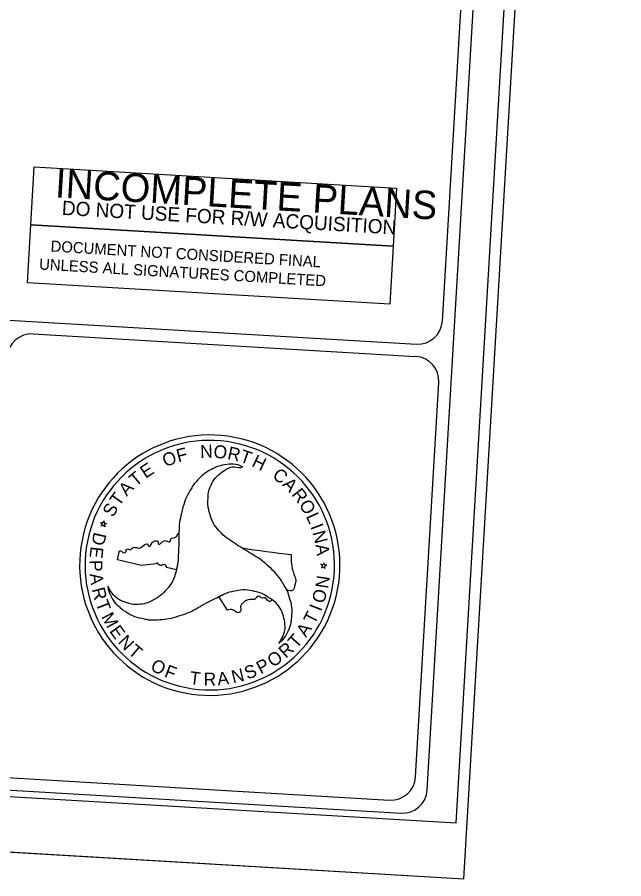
# Model space of a CAD drawing. Extents: x 1998567 to 2027801, y 439108 to 451079.
# Drawn here: x 2018763 to 2021220, y 439108 to 442597 of the extents above; entities that cross this region are included whole.
import ezdxf

# ---------------------------------------------------------------- set-up
doc = ezdxf.new("R2010")
doc.units = 0
for name, color, linetype in [('Sheet Cutting Line CELL', 7, 'Continuous'), ('Sheet Plot Border Inside CELL', 7, 'Continuous'), ('Sheet Plot Border Outside CELL', 7, 'Continuous'), ('Sheet Sticker Exception Certification CELL', 7, 'Continuous'), ('Sheet Sticker Incomplete CELL', 7, 'Continuous'), ('Sheet Title CELL', 7, 'Continuous')]:
    doc.layers.add(name, color=color, linetype=linetype)

msp = doc.modelspace()

# ---------------------------------------------------------------- linework, layer by layer
at = {"layer": 'Sheet Cutting Line CELL'}
msp.add_line((2003762.2, 440098.6), (2020573, 439107.6), dxfattribs=at)
at = {"layer": 'Sheet Plot Border Inside CELL'}
msp.add_lwpolyline([(2003905.2, 440314.9), (2020541.3, 439334.2), (2021162.2, 449866.9), (2004526.1, 450847.6)], close=True, dxfattribs=at)
at = {"layer": 'Sheet Plot Border Outside CELL'}
msp.add_lwpolyline([(2021220.3, 450088.4), (2004409.5, 451079.4), (2003762.2, 440098.6), (2020573, 439107.6)], close=True, dxfattribs=at)
at = {"layer": 'Sheet Sticker Exception Certification CELL'}
for p, q in [((2018804.5, 441521.7), (2018818.3, 441756.3)), ((2018818.3, 441756.3), (2020285.8, 441669.8)), ((2020285.8, 441669.7), (2020272, 441435.1)), ((2020272, 441435.2), (2018804.5, 441521.7))]:
    msp.add_line(p, q, dxfattribs=at)
at = {"layer": 'Sheet Sticker Incomplete CELL'}
msp.add_lwpolyline([(2018818.3, 441756.3), (2018832.2, 441990.9), (2020299.6, 441904.4), (2020285.8, 441669.8)], close=True, dxfattribs=at)
at = {"layer": 'Sheet Title CELL'}
for p, q in [((2006204.7, 442108.3), (2020380.1, 441272.7)), ((2018827.5, 441314.1), (2020377.1, 441222.8)), ((2019677.5, 440777.1), (2019676.3, 440776.2)), ((2019677.5, 440777.1), (2019676.3, 440776.2)), ((2019107.5, 440544.3), (2019101.4, 440551.1)), ((2019101.4, 440551.1), (2019110.4, 440549.3)), ((2019110.4, 440549.3), (2019114.5, 440557.1)), ((2019114.5, 440557.1), (2019115.9, 440548.3)), ((2019103.3, 440536.2), (2019107.5, 440544.3)), ((2019111.2, 440540.3), (2019103.3, 440536.2)), ((2019117.5, 440533.5), (2019111.2, 440540.3)), ((2019115.9, 440548.3), (2019124.8, 440546.5)), ((2019124.8, 440546.5), (2019116.4, 440542.6)), ((2019116.4, 440542.6), (2019117.5, 440533.5)), ((2019671.3, 440448.6), (2019671.3, 440448.6)), ((2019169.2, 440399.7), (2019176.3, 440430.6)), ((2019266.6, 440377), (2019169.2, 440399.7)), ((2019326.1, 440382.6), (2019266.6, 440377)), ((2020002.6, 440379.7), (2019993.7, 440381.4)), ((2019993.7, 440381.4), (2020000, 440374.8)), ((2020000, 440374.8), (2019995.8, 440366.7)), ((2020006.9, 440387.4), (2020002.6, 440379.7)), ((2020008.4, 440378.6), (2020006.9, 440387.4)), ((2020017.2, 440377.2), (2020008.4, 440378.6)), ((2020008.9, 440373.1), (2020017.2, 440377.2)), ((2019409, 440359.4), (2019368.1, 440367.8)), ((2019995.8, 440366.7), (2020003.7, 440370.6)), ((2020003.7, 440370.6), (2020009.9, 440364)), ((2020009.9, 440364), (2020008.9, 440373.1)), ((2020060.8, 440277.7), (2020060.8, 440277.7)), ((2019614.6, 440195), (2019580.3, 440250.5)), ((2019580.3, 440250.5), (2019580.3, 440250.5))]:
    msp.add_line(p, q, dxfattribs=at)
for points in [[(2020423.9, 439467), (2021030, 449749)], [(2020485.8, 441366.5), (2020977.2, 449702.2)], [(2020376.9, 439519.9), (2020471.1, 441117.1)], [(2005543.8, 440243.8), (2020318.2, 439372.9)], [(2018721.7, 439517.3), (2020271.2, 439425.9)]]:
    msp.add_lwpolyline(points, dxfattribs=at)
for centre, radius, start, end in [((2020386, 441373), 100, 266.6264, 356.6264), ((2018821.7, 441214.3), 100, 86.6264, 176.6264), ((2020371.3, 441123.4), 100, 356.6264, 86.6264), ((2019543.3, 440377.7), 527.2, 349.0476, 169.0476), ((2019543.3, 440377.7), 505.2, 349.0476, 169.0476), ((2020146.1, 443187.2), 2779.4, 254.7261, 254.8256), ((2019543.3, 440377.7), 527.2, 169.0476, 349.0476), ((2019543.3, 440377.7), 505.2, 169.0476, 349.0476), ((2020146.1, 443187.2), 2779.4, 260.1651, 264.3711), ((2020277.2, 439526.2), 100, 266.6264, 356.6264), ((2020324.1, 439473.3), 100, 266.6264, 356.6264)]:
    msp.add_arc(centre, radius, start, end, dxfattribs=at)
for points in [[(2019676.3, 440776.2), (2019665.3, 440781.6), (2019630.7, 440786.8), (2019593.5, 440782.4), (2019590.1, 440781.3), (2019570.8, 440775.5), (2019549.6, 440765.3), (2019516.4, 440744.2), (2019488.6, 440715.7), (2019477.3, 440703.4), (2019467.7, 440687.4), (2019449.1, 440653.1), (2019436.3, 440619), (2019426, 440578.2), (2019419.6, 440541.8), (2019418.5, 440503.7), (2019417.7, 440465.2), (2019416.1, 440428), (2019413.9, 440389.7), (2019406.9, 440352.7), (2019406.1, 440349.5), (2019391.9, 440311.4), (2019369.3, 440279.9), (2019343.1, 440254.9), (2019328.4, 440243.9), (2019308.5, 440233.8), (2019297.1, 440227.8), (2019271.3, 440220.4), (2019234.3, 440219), (2019200, 440227.7), (2019170.8, 440241.5), (2019147.2, 440264), (2019130.7, 440293)], [(2019822.4, 440062.2), (2019832, 440068.9), (2019854.2, 440096.3), (2019868.9, 440130.7), (2019870.1, 440134.2), (2019874.2, 440153.9), (2019876.1, 440177.6), (2019874.8, 440216.8), (2019863.5, 440254.9), (2019858.8, 440271), (2019849.6, 440287.5), (2019829.3, 440320.6), (2019806.2, 440348.8), (2019775.9, 440377.9), (2019747.5, 440401.4), (2019715.1, 440422), (2019682.3, 440441.7), (2019651.1, 440461.6), (2019618.5, 440482.8), (2019590.2, 440507.2), (2019588, 440509.7), (2019561.6, 440541.3), (2019545.9, 440576.6), (2019537.1, 440611.6), (2019535.4, 440629.6), (2019536.6, 440652.1), (2019536.8, 440665.1), (2019543.6, 440690.8), (2019560.9, 440724), (2019585.3, 440749), (2019611.9, 440767.2), (2019643.4, 440776.4), (2019676.3, 440776.2), (2019677.5, 440777.1)], [(2019176.3, 440430.6), (2019175.7, 440433.7), (2019181.6, 440436.1), (2019195, 440427.3), (2019203.6, 440432.1), (2019204.5, 440438.5), (2019211.6, 440443.7), (2019221.1, 440439.7), (2019232.4, 440449.5), (2019241.1, 440449.9), (2019258.6, 440446.5), (2019283.3, 440463.3), (2019292.3, 440462.9), (2019293.4, 440456.9), (2019298.6, 440454.8), (2019310.8, 440470.3), (2019313.6, 440472.3), (2019331.1, 440475.6), (2019334.8, 440471.7), (2019334.5, 440463.8), (2019336.5, 440461.8), (2019342.6, 440464.6), (2019351.6, 440472.4), (2019366.3, 440476.7), (2019381.1, 440472), (2019386.1, 440483.9), (2019406.2, 440492.4), (2019411.3, 440498.9), (2019413.7, 440506.1)], [(2019418.5, 440504.7), (2019418.5, 440503.7), (2019417.7, 440465.2), (2019416.1, 440428), (2019413.9, 440389.7), (2019408.9, 440359.5)], [(2019856.1, 440277.2), (2019849.6, 440287.5), (2019829.3, 440320.6), (2019806.2, 440348.8), (2019775.9, 440377.9), (2019747.5, 440401.4), (2019715.1, 440422), (2019682.3, 440441.7), (2019671.3, 440448.6)], [(2019873.4, 440421.1), (2019874.1, 440385.1), (2019884.3, 440341), (2019891.7, 440316.5), (2019887.7, 440297.4), (2019878.8, 440275.4), (2019856.2, 440277.4)], [(2019368.1, 440367.8), (2019365.6, 440376.1), (2019358.1, 440380), (2019346.2, 440376.4), (2019338.2, 440378.4), (2019330.5, 440386.6), (2019326.1, 440382.6)], [(2019130.7, 440293), (2019132.1, 440280.6), (2019144.7, 440247.9), (2019166.9, 440217.9), (2019169.5, 440215.8), (2019184.5, 440201.6), (2019203.9, 440188.6), (2019238.8, 440170), (2019277.1, 440160.7), (2019293.4, 440156.8), (2019312.9, 440156.5), (2019351, 440157.7), (2019386.8, 440163.4), (2019427.6, 440175.1), (2019461.9, 440187.7), (2019495.9, 440205.8), (2019529.5, 440224.6), (2019562.7, 440241.5), (2019597, 440258.6), (2019632.4, 440271.3), (2019636.2, 440272), (2019676.4, 440278.9), (2019714.5, 440275), (2019748.9, 440265.2), (2019766.4, 440257.8), (2019784.5, 440245.3), (2019796.1, 440238.7), (2019814.9, 440219.9), (2019834.5, 440188.6), (2019844.2, 440154.9), (2019846.8, 440122.4), (2019839.1, 440090.7), (2019822.4, 440062.2)], [(2019580.3, 440250.5), (2019597, 440258.6), (2019632.4, 440271.3), (2019636.2, 440272), (2019676.4, 440278.9), (2019714.5, 440275), (2019748.9, 440265.2), (2019766.4, 440257.8), (2019784.5, 440245.3), (2019795.2, 440239)], [(2019795, 440238.9), (2019788.5, 440230.8), (2019780.6, 440231.7), (2019769, 440245.2), (2019751.6, 440245.1), (2019744.8, 440251), (2019739.8, 440252.1), (2019724.7, 440239.3), (2019707.5, 440238.8), (2019676.8, 440224.2), (2019669, 440213.8), (2019666.2, 440188.6), (2019658.7, 440184.9), (2019650.9, 440187.7), (2019635.6, 440197.3), (2019614.6, 440195)]]:
    msp.add_spline(points, degree=3, dxfattribs=at)

# ---------------------------------------------------------------- texts
at = {"layer": 'Sheet Sticker Exception Certification CELL'}
for s, p in [('DOCUMENT NOT CONSIDERED FINAL', (2018897.5, 441648)), ('UNLESS ALL SIGNATURES COMPLETED', (2018851, 441575.2))]:
    msp.add_text(s, height=45, rotation=356.6264, dxfattribs=at).set_placement(p)
at = {"layer": 'Sheet Sticker Incomplete CELL'}
for s, height, p in [('INCOMPLETE PLANS', 115.2, (2018914.6, 441867.8)), ('DO NOT USE FOR R/W ACQUISITION', 57.6, (2018942.9, 441796.6))]:
    msp.add_text(s, height=height, rotation=356.6264, dxfattribs=at).set_placement(p)
at = {"layer": 'Sheet Title CELL'}
for s, height, rotation, p in [('N', 52.6, 2.0313, (2019505.3, 440811.6)), ('O', 52.7, 354.5332, (2019556.6, 440813.1)), ('O', 52.6, 21.2651, (2019363.5, 440774.2)), ('F', 52.7, 14.1183, (2019415.5, 440794.1)), ('R', 52.6, 347.9233, (2019612, 440807.8)), ('T', 52.7, 341.2737, (2019661.2, 440797.3)), ('E', 52.4, 33.2045, (2019283.1, 440727.1)), ('H', 52.5, 334.1889, (2019709.8, 440780.4)), ('T', 52.4, 40.3201, (2019243.8, 440694)), ('C', 52.4, 321.8466, (2019793.2, 440734.7)), ('A', 52.5, 314.3496, (2019834.3, 440702.1)), ('A', 52.7, 47.3753, (2019206.9, 440654)), ('R', 52.5, 307.9856, (2019872.1, 440663.6)), ('T', 52.7, 54.4277, (2019176.5, 440612.6)), ('S', 52.5, 60.8038, (2019151.9, 440569)), ('O', 52.7, 300.866, (2019902.9, 440623.9)), ('L', 52.4, 294.6323, (2019931.7, 440575.8)), ('I', 52.6, 290.643, (2019949.7, 440534.1)), ('N', 52.5, 284.9429, (2019958.4, 440510)), ('D', 52.6, 256.9006, (2019074.5, 440514)), ('E', 52.3, 263.1884, (2019061.3, 440455.1)), ('A', 52.6, 277.5109, (2019971.3, 440460.1)), ('P', 52.6, 270.7208, (2019055.6, 440398.2)), ('A', 52.5, 277.3134, (2019056.3, 440342.1)), ('N', 52.6, 81.2557, (2020022.4, 440280.7)), ('R', 52.6, 284.3821, (2019064.9, 440280.4)), ('O', 52.4, 74.0077, (2020005.5, 440219.5)), ('T', 52.5, 291.0326, (2019079.8, 440224.4)), ('I', 52.7, 68.872, (2019993.6, 440187.9)), ('M', 52.4, 298.2676, (2019102.1, 440169)), ('T', 52.5, 63.2221, (2019967.1, 440134.8)), ('E', 52.4, 305.7344, (2019134.7, 440110.6)), ('A', 52.7, 56.1377, (2019933, 440082.7)), ('N', 52.7, 312.7059, (2019168.4, 440065)), ('T', 52.4, 48.0507, (2019893.9, 440037.7)), ('T', 52.5, 319.5479, (2019209, 440021.8)), ('R', 52.6, 41.9509, (2019851.1, 439998.3)), ('O', 52.7, 34.7618, (2019799.1, 439961.7)), ('O', 52.5, 332.8516, (2019299, 439954.8)), ('P', 52.5, 28.0698, (2019749.7, 439934.8)), ('F', 52.5, 340.0169, (2019356, 439926.6)), ('N', 52.4, 13.6675, (2019638, 439898.6)), ('S', 52.3, 20.8779, (2019695.5, 439913.8)), ('T', 52.4, 352.9261, (2019459.1, 439896.5)), ('R', 52.6, 359.8827, (2019518.3, 439889.8)), ('A', 52.4, 6.6358, (2019576.4, 439890.5))]:
    msp.add_text(s, height=height, rotation=rotation, dxfattribs=at).set_placement(p)

doc.saveas('drawing.dxf')
